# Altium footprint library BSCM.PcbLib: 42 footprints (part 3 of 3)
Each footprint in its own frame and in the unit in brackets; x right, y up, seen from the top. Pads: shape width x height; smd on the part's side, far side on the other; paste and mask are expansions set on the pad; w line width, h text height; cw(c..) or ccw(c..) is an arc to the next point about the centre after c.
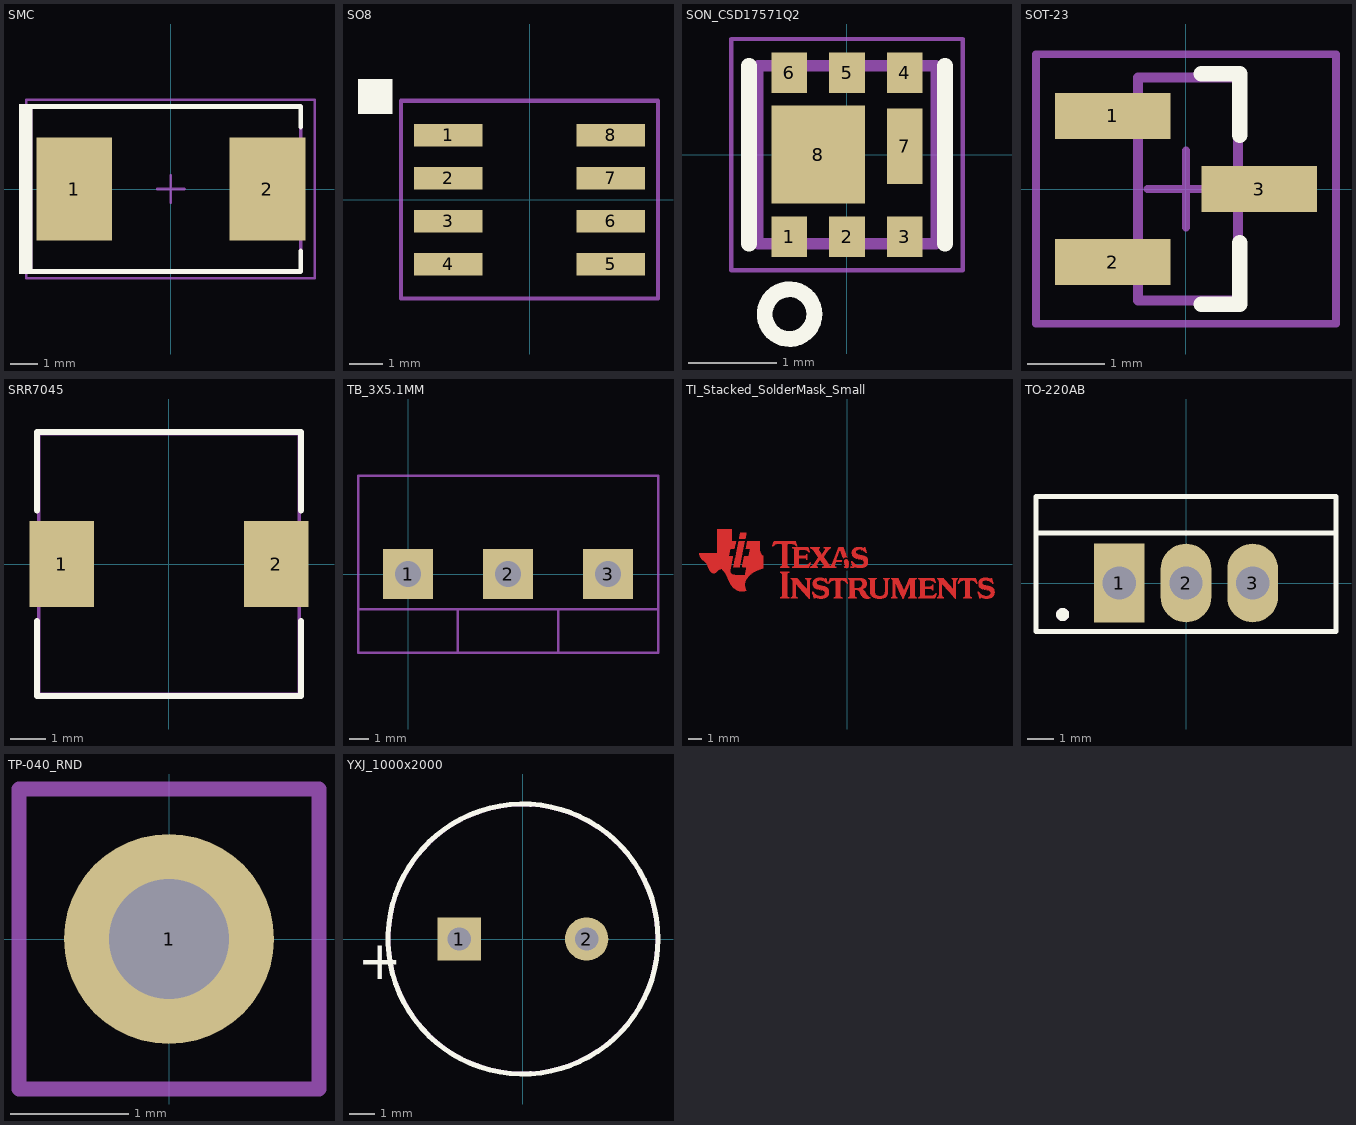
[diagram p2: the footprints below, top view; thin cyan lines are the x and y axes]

## SMC [mil] "Molded Diode, 2-Leads, Body 6.9x5.8mm, IPC Medium Density, based on OnSemi component dimensions and land patterns"
height 94.88
pads (2):
  rect 110x150 smd: 1(-140.49,0) 2(140.49,0)
Top Overlay:
  rectangle: -221,-123.5 -201,123.5
  lines w7: -210,-120 189,-120 189,-90.25 ; -210,120 189,120 189,90.25
Mechanical 5:
  rectangle: -221,-123.5 -201,123.5
  lines w5: -210,-120 189,-120 189,120 -210,120
  text ".Designator" at -37.66,-18 h40
Mechanical 15:
  lines w3.94: -19.69,0 19.68,0 ; 0,-19.68 0,19.68 ; -210.46,-129.92 209.38,-129.92 209.38,129.92 -210.46,129.92 -210.46,-129.92
3D body: height 91.35, standoff 0.6, extent -156.49,-116.13 156.5,116.15

## SO8 [mil]
pads (8):
  rect 80x26 smd: 1(-95,75) 2(-95,25) 3(-95,-25) 4(-95,-75) 5(94,-75) 6(94,-25) 7(94,25) 8(94,75)
Top Overlay:
  region: -160,100 -160,140 -200,140 -200,100
Mechanical 5:
  lines w5: -150,-115 149,-115 149,115 -150,115 -150,-115
  text ".Designator" at -18,37 h40
  text "*" at -55.9,51.4 h40

## SON_CSD17571Q2 [mm] "SON, MOSFET, N-CH, 30V, 22A, SON 2X2 MM"
height 0.85
pads (8):
  rect 0.4x0.455 smd mask+0.038: 1(-0.65,-0.923) 2(0,-0.923) 5(0,0.923) 6(-0.65,0.923)
  rect 0.4x0.455 smd: 3(0.65,-0.923) 4(0.65,0.923)
  rect 0.4x0.85 smd mask+0.038: 7(0.65,0.096)
  rect 1.05x1.1 smd mask+0.038: 8(-0.325,0)
Top Overlay:
  circle w0.178: c-0.646,-1.792 r0.279
  lines w0.178: -1.1,-1 -1.1,1 ; 1.1,-1 1.1,1
  text ".Designator" at -1.727,-0.432 h1.02
Mechanical 5:
  circle w0.127: c-0.646,-1.792 r0.279
  lines w0.127: -1,-1 -1,1 1,1 1,-1 -1,-1
  text ".Designator" at -1.397,-0.584 h1.02
Mechanical 15:
  lines w0.05: -1.3,-1.3 1.3,-1.3 1.3,1.3 -1.3,1.3 -1.3,-1.3
3D body: height 0.85, standoff 0, extent -1,-1 1,0.975

## SOT-23 [mm] "SOT23, 3-Leads, Body 2.9x1.3mm, Pitch 0.95mm, Lead Span 2.5mm, IPC Medium Density"
height 1.1
pads (3):
  rect 1.5x0.6 smd: 1(-0.95,0.95) 2(-0.95,-0.95) 3(0.95,0)
Top Overlay:
  lines w0.2: 0.2,-1.5 0.7,-1.5 0.7,-0.7 ; 0.2,1.5 0.7,1.5 0.7,0.7
Mechanical 5:
  lines w0.127: -1.16,-1.15 -1.16,-0.75 -0.625,-0.75 -0.625,0.75 -1.16,0.75 -1.16,1.15 -0.625,1.15 -0.625,1.45 0.675,1.45 0.675,0.2 1.21,0.2 1.21,-0.2 0.675,-0.2 0.675,-1.45 -0.625,-1.45 -0.625,-1.15 -1.16,-1.15
  text ".Designator" at -0.175,1.225 h0.64
Mechanical 15:
  lines w0.1: -0.5,0 0.5,0 ; 0,-0.5 0,0.5 ; -1.95,-1.75 1.95,-1.75 1.95,1.75 -1.95,1.75 -1.95,-1.75
3D body: height 1, standoff 0, extent -1.16,-1.45 1.21,1.45

## SRR7045 [mm] "BOURNS"
height 4.8
pads (2):
  rect 1.8x2.4 smd: 1(-3,0) 2(3,0)
Top Overlay:
  lines w0.17: -3.7,-1.6 -3.7,-3.7 3.7,-3.7 3.7,-1.6 ; -3.7,1.5 -3.7,3.7 3.7,3.7 3.7,1.5
Mechanical 5:
  lines w0.1: -3.65,-3.65 -3.65,3.65 3.65,3.65 3.65,-3.65 -3.65,-3.65
  text ".Designator" at -0.356,0.737 h1.02
3D body: height 1, standoff 0, extent -3.649,-3.649 3.649,3.649
3D body: height 4.8, standoff 1, extent -3.56,-3.56 3.56,3.56

## TB_3X5.1MM [mil]
pads (3):
  rect 100x100 hole 52: 1(0,0) 2(200,0) 3(400,0)
Mechanical 5:
  lines w5: -100,-70 500,-70 ; 99,-157 99,-70 ; 300,-157 300,-70 ; -100,-157 -100,197 500,197 500,-157 -100,-157
  text ".Designator" at 148,58 h40

## TI_Stacked_SolderMask_Small [mil]
pads (1):
  rect 850x200 on Top Solder paste-125 mask-125: 0(0,0)
Top Layer:
  drawing of 18 lines, arcs and shapes, not listed

## TO-220AB [mil] "Copied from Altium's version of TO3B"
height 763.78
pads (3):
  rect 76x118.11 hole 50: 1(-100,0)
  oval 76x118.11 hole 50: 2(0,0) 3(100,0)
Top Overlay:
  circle w9.84: c-185.04,-47.24 r4.92
  lines w7.87: -225,75 225,75 ; -225,-72.83 -225,130 225,130 225,-72.83 -225,-72.83
Mechanical 5:
  circle w9.84: c-185.04,-47.24 r4.92
  lines w5: -225,75 225,75 ; -225,-72.83 225,-72.83 225,130 -225,130 -225,-72.83
  text ".Designator" at 26,-94 h40
Mechanical 15:
  lines w3.94: -19.69,0 19.68,0 ; 0,-19.69 0,19.68
3D body: height 764.72, standoff -390, extent -220.72,-58.85 220.74,125.8

## TP-040_RND [mil]
pads (1):
  round 70 / inner round 62 / far side round 62 hole 40: 1(0,0)
Mechanical 5:
  lines w5: -50,-50 -50,50 50,50 50,-50 -50,-50

## YXJ_1000x2000 [mm] "RUBYCON"
height 22
pads (2):
  rect 1.7x1.7 hole 0.914: 1(-2.5,0)
  round 1.7 hole 0.914: 2(2.5,0)
Top Overlay:
  circle w0.2: c0,0 r5.3
  text "+" at -6.477,-1.575 h1.52
Mechanical 5:
  circle w0.1: c0,0 r5.25
  text "+" at -6.7,-0.8 h1.02
  text ".Designator" at 1.168,0.432 h1.02
3D body: height 22.01, standoff -4, extent -5.209,-5.241 5.24,5.242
